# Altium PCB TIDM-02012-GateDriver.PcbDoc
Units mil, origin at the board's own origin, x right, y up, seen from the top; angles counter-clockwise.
Board outline 2300 x 940 mil, 4 copper layers (Top Layer, Layer 1, Layer 2, Bottom Layer), stack 52.2 mil thick; 39 components, 15 nets, 65 pads, 17 vias.
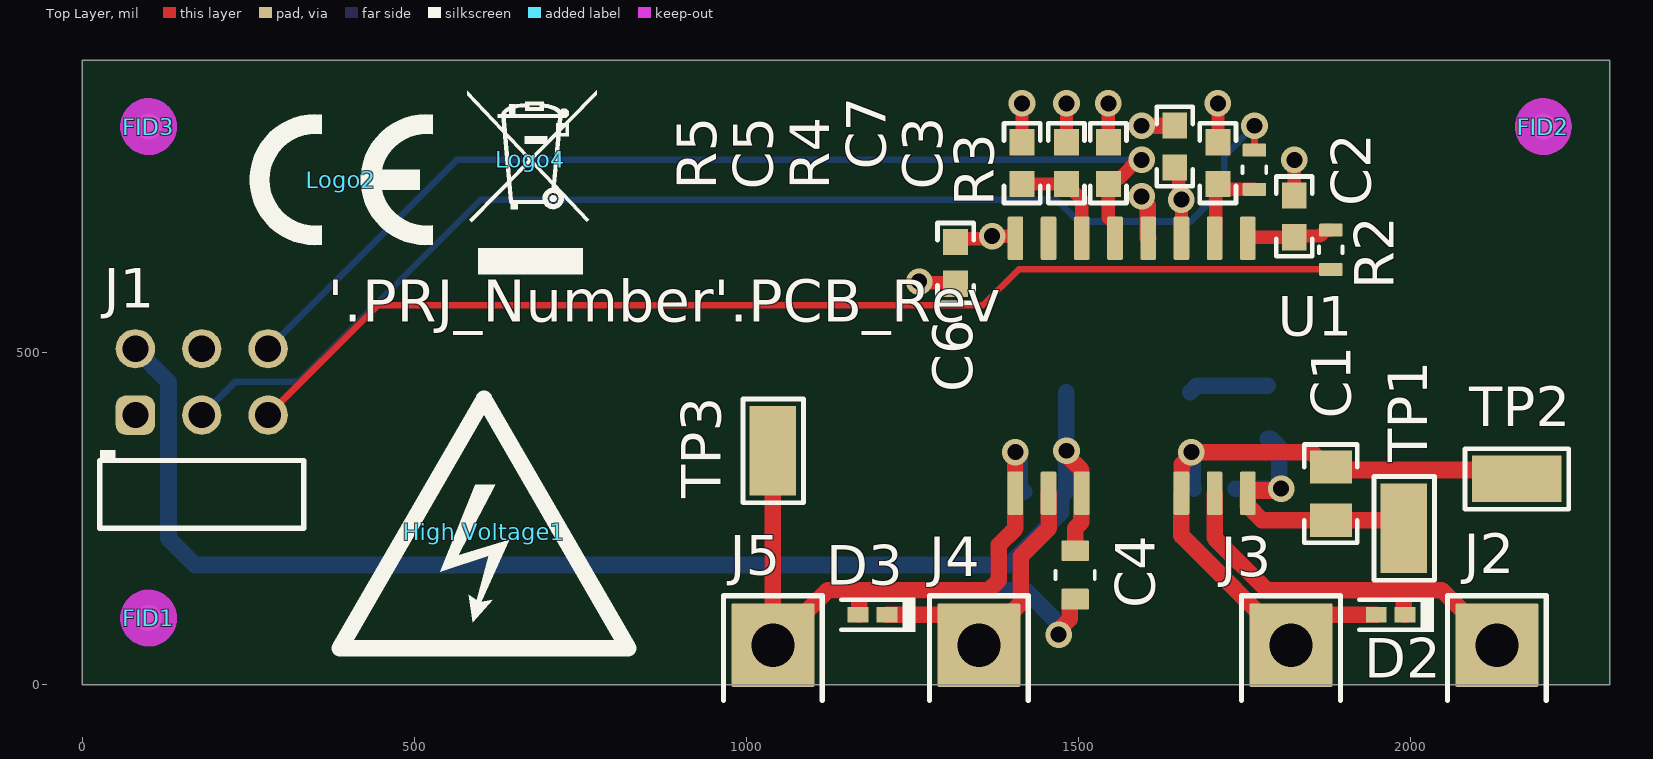
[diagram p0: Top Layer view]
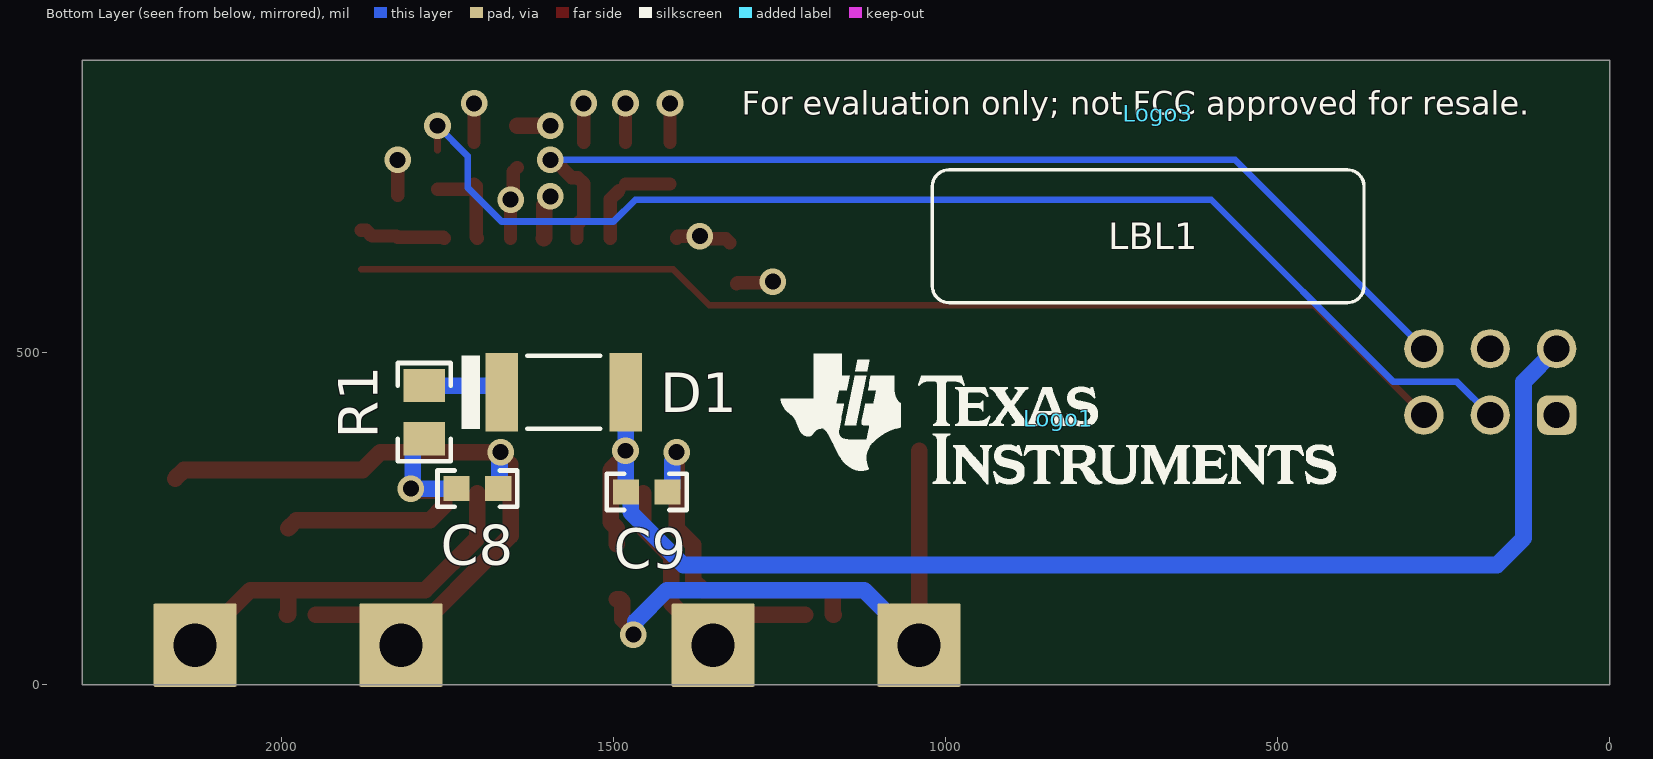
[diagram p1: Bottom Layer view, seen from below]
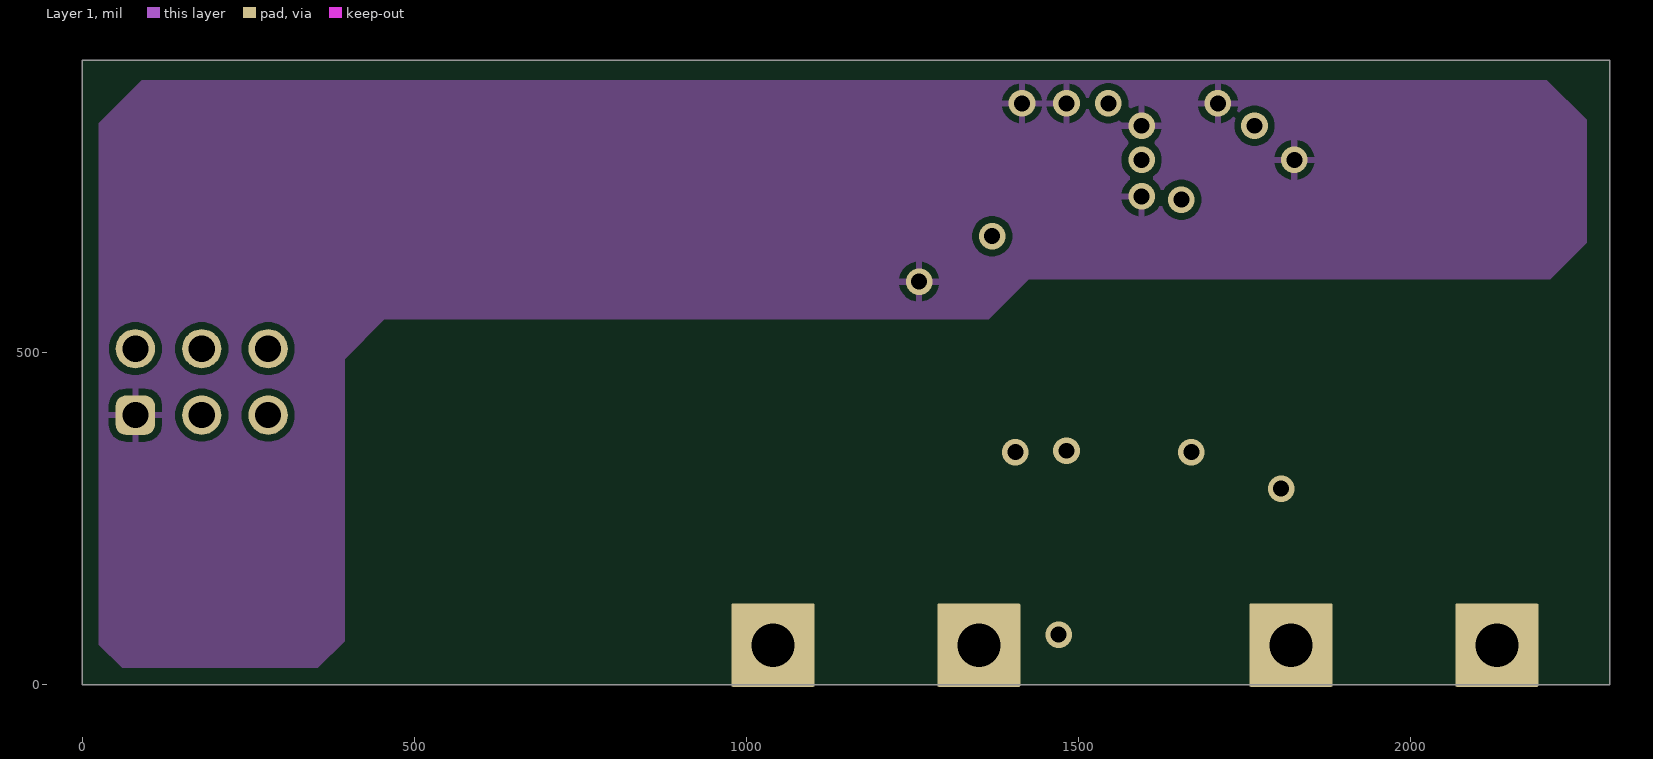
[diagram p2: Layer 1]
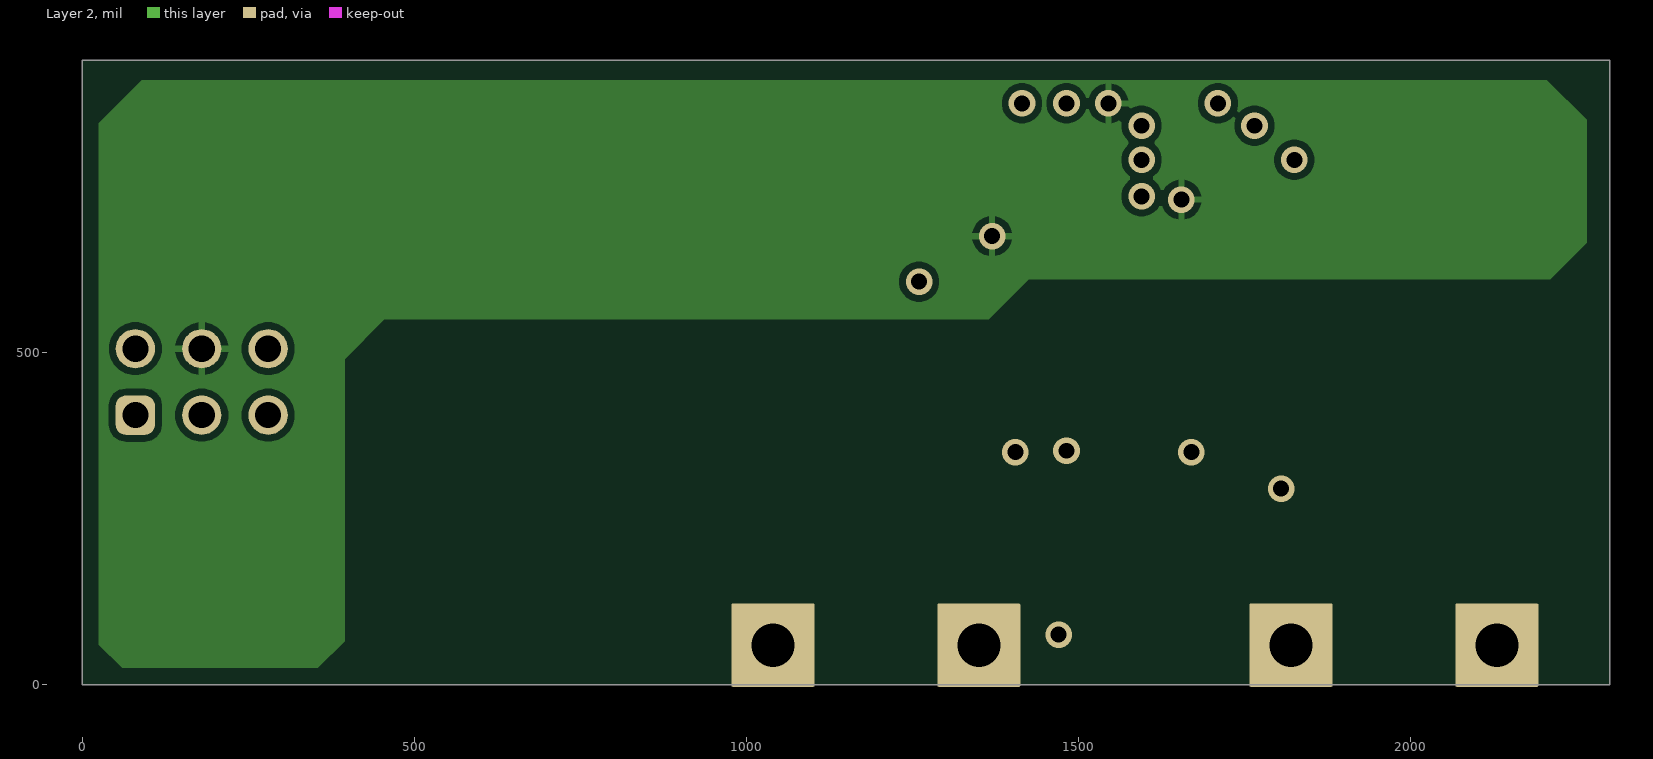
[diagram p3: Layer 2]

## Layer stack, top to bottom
Top Solder: solder mask 0.4, Solder Resist, Dk 3.5
Top Layer: signal copper 2.8
Dielectric 1: prepreg 5.6, PP-006, Dk 4.1
Layer 1: signal copper 2.8
Dielectric1: core 29.8, FR-4 High Tg, Dk 4.8
Layer 2: signal copper 2.8
Dielectric 2: prepreg 5.6, PP-006, Dk 4.1
Bottom Layer: signal copper 2.8
Bottom Solder: solder mask 0.4, Solder Resist, Dk 3.5

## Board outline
0,0 0,940 2300,940 2300,0

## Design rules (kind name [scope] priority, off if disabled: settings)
AcuteAngle [All] p1: minimum=4.50000000000000E+0001 checktracksonly=FALSE
AssemblyTestPointUsage [All] p1: valid=2
BoardOutlineClearance BoardOutlineClearance_MountingHoles [OnCopper and InComponentClass('Mounting Holes')] p1: gap=39.37 ignorepadtopadclearanceinfootprint=FALSE
BoardOutlineClearance BoardOutlineClearance_Poly [OnCopper and IsPoly] p2: gap=25 ignorepadtopadclearanceinfootprint=FALSE
BoardOutlineClearance [OnCopper and Not InComponentClass('Logo') and not InComponentClass('FiducialMark') and not InRegion(1000,500,4000,800) and not InPoly] p3: gap=40 ignorepadtopadclearanceinfootprint=FALSE
Clearance Clearance_Keepouts [((IsTrack Or IsArc) And Not InPoly) And IsFree and IsKeepOut vs ((IsTrack Or IsArc) And Not InPoly) And IsFree and IsKeepOut] p1: gap=0 ignorepadtopadclearanceinfootprint=FALSE
Clearance Clearance_Poly [InPolygon] p2: gap=10 ignorepadtopadclearanceinfootprint=TRUE
Clearance Clearance_FiducialMark [IsKeepOut and InComponentClass('FiducialMark') vs IsPad and InComponentClass('FiducialMark')] p3: gap=0 ignorepadtopadclearanceinfootprint=FALSE
Clearance [All] p4: gap=7.87 ignorepadtopadclearanceinfootprint=TRUE
ComponentClearance ComponentClearance_MountingHoles_FiducialMarks [InComponentClass('Mounting Holes') vs InComponentClass('FiducialMark')] p1: gap=50 collisioncheckmode=3 verticalgap=10 showdistances=FALSE
ComponentClearance ComponentClearance_Shunt [InComponentClass('Header') vs InComponentClass('Shunt')] p2: gap=0 collisioncheckmode=3 verticalgap=0 showdistances=FALSE
ComponentClearance ComponentClearance_Logo [InComponentClass('Logo')] p3: gap=30 collisioncheckmode=3 verticalgap=10 showdistances=FALSE
ComponentClearance ComponentClearance_ScrewToNut [(HasFootprint('NY PMS 440 0025 PH')) vs (HasFootprint('Keystone_1902C'))] p4: gap=5 collisioncheckmode=3 verticalgap=10 showdistances=FALSE
ComponentClearance ComponentClearance_MountingHoles [InComponentClass('Mounting Holes')] p5: gap=100 collisioncheckmode=3 verticalgap=100000 showdistances=FALSE
ComponentClearance ComponentClearance_SmallPassives [HasFootprint('0201*') or HasFootprint('0402*') or HasFootprint('0508') or HasFootprint('0603*') or HasFootprint('0612') or HasFootprint('0805*') or HasFootprint('0815*') or HasFootprint('0830*') or HasFootprint('1206*') or HasFootprint('1210*') or HasFootprint('1808*') or HasFootprint('1812*') or HasFootprint('1825*') or HasFootprint('2010*') or HasFootprint('2220*') or HasFootprint('2225*') or HasFootprint('2512*') or HasFootprint('2728*') or HasFootprint('3518*') vs HasFootprint('0201*') or HasFootprint('0402*') or HasFootprint('0508') or HasFootprint('0603*') or HasFootprint('0612') or HasFootprint('0805*') or HasFootprint('0815*') or HasFootprint('0830*') or HasFootprint('1206*') or HasFootprint('1210*') or HasFootprint('1808*') or HasFootprint('1812*') or HasFootprint('1825*') or HasFootprint('2010*') or HasFootprint('2220*') or HasFootprint('2225*') or HasFootprint('2512*') or HasFootprint('2728*') or HasFootprint('3518*')] p6: gap=14.96 collisioncheckmode=3 verticalgap=10 showdistances=FALSE
ComponentClearance ComponentClearance_THtoSMT [IsThruComponent vs IsSMTComponent] p7: gap=30 collisioncheckmode=3 verticalgap=30 showdistances=FALSE
ComponentClearance ComponentClearance_THtoTH [IsThruComponent vs IsThruComponent] p8: gap=20 collisioncheckmode=3 verticalgap=30 showdistances=FALSE
ComponentClearance [All] p9: gap=20 collisioncheckmode=3 verticalgap=10 showdistances=FALSE
DiffPairsRouting [All] p1: maxlimit=100 minlimit=10 mostfreqgap=10 toplayer_minwidth=15 toplayer_maxwidth=15 toplayer_prefwidth=15 midlayer1_minwidth=15 midlayer1_maxwidth=15 midlayer1_prefwidth=15 midlayer2_minwidth=15 midlayer2_maxwidth=15 midlayer2_prefwidth=15 bottomlayer_minwidth=15 bottomlayer_maxwidth=15 bottomlayer_prefwidth=15 maxuncoupledlength=1000
FabricationTestPointUsage TestPointUsage [All] p1: valid=2 allowmultiple=FALSE
FabricationTestpoint Testpoint [All] p1: side=3 testpointundercomponent=TRUE minsize=40 maxsize=100 preferedsize=60 minholesize=0 maxholesize=40 preferedholesize=32 testpointgrid=1 allowsidetop=TRUE allowsidebottom=TRUE usegrid=TRUE gridtolerance=0.01
FanoutControl Fanout_LCC [IsLCC] p1: bgadir=Out bgaviamode=Centered fanoutstyle=Auto fanoutdirection=Alternating viagrid=1 // Fanout_LCC (Default Rule)
FanoutControl Fanout_BGA [IsBGA] p2: bgadir=Out bgaviamode=Centered fanoutstyle=Auto fanoutdirection=Alternating viagrid=1 // Fanout_BGA (Default Rule)
FanoutControl Fanout_Default [All] p4: bgadir=Out bgaviamode=Centered fanoutstyle=Auto fanoutdirection=Alternating viagrid=1 // Fanout_Default (Default Rule)
FanoutControl Fanout_Small [(CompPinCount < 5)] p5: bgadir=Out bgaviamode=Centered fanoutstyle=Auto fanoutdirection=OutThenIn viagrid=1 // Fanout_Small (Default Rule)
HoleSize [All] p1: absolutevalues=TRUE maxlimit=251 minlimit=7.87 maxpercent=80.000 minpercent=20.000
MinimumAnnularRing MinimumAnnularRing_ThermalPadVias [IsVia and InAnyComponent] p1: minimumring=5.91
MinimumAnnularRing [All] p2: minimumring=7.87
MinimumSolderMaskSliver MinimumSolderMaskSliver_Logo [InComponentClass('Logo') vs InComponentClass('Logo')] p1: minsoldermaskwidth=0.7
MinimumSolderMaskSliver [All] p2: minsoldermaskwidth=3.94
PlaneConnect [All] p1: planeconnectstyle=Relief reliefexpansion=10 reliefentries=4 reliefconductorwidth=10 reliefairgap=10
PolygonConnect [All] p1: connectstyle=Relief reliefconductorwidth=10 reliefentries=4 polygonreliefangle="90 Angle" airgapwidth=10
RoutingVias ThermalPadVias [IsVia and InAnyComponent] p1: holewidth=7.87 width=19.68 viastyle="Through Hole" minholewidth=7.87 minwidth=19.68 maxholewidth=12.99 maxwidth=23.62
RoutingVias [All] p2: holewidth=16 width=34 viastyle="Through Hole" minholewidth=7.87 minwidth=24 maxholewidth=40 maxwidth=65
SilkToBoardRegionClearance [Not ((IsComment or IsDesignator) And (Hide <> 'False')) and not InRegion(1000,500,4000,800)] p1:
SilkToSilkClearance SilkToSilkClearance_Pb-FreeLogo [(HasFootprint('Pb-Free_Overlay_Medium') OR HasFootprint('Pb-Free_Overlay_Small')) vs (HasFootprint('Pb-Free_Overlay_Medium') OR HasFootprint('Pb-Free_Overlay_Small'))] p1: silktosilkclearance=0
SilkToSilkClearance [All] p2: silktosilkclearance=3.94
SilkToSolderMaskClearance SilkToComponentPadClearance [(IsPad or IsFill or IsRegion) and InAnycomponent] p1: minsilkscreentomaskgap=5 clearancetoexposedcopper=TRUE
SilkToSolderMaskClearance "Silk to Solder Mask Opening" [All] p2: minsilkscreentomaskgap=3.94 clearancetoexposedcopper=FALSE
SolderMaskExpansion [All] p1: expansion=1.97 istentingtop=FALSE
UnRoutedNet [All] p1: checkbadconnections=TRUE
Width [All] p1: maxlimit=100 minlimit=6 preferedwidth=10 checkconnectedcopper=TRUE
14 further rules are at their usual default settings.

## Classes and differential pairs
component class Header: J1
component class Logo: Logo1
component class TIDM-02012-GateDriver_Hardware: FID1 FID2 FID3 "High Voltage1" LBL1 Logo1 Logo2 Logo3 Logo4 ZZ1 ZZ2 ZZ3 ZZ4
component class FiducialMark: FID1 FID2 FID3
component class AssemblyNote: ZZ1 ZZ2 ZZ3 ZZ4
component class Label: LBL1

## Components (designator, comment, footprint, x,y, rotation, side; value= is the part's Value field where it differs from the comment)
C1 "C2012X7R1H225M125AC" 0805_HV 1880,287.38 r90 top value=2.2uF
C2 "C0603C470J1GACAUTO" 0603 1825,705 r90 top value=47pF
C3 "C0603C470J1GACAUTO" 0603 1710,785 r90 top value=47pF
C4 "C2012X7R1H475K125AC" FP-C2012X7R1H475K125AC_0805-MFG 1495,165 r90 top
C5 "CGA3E2X7R2A222K080AA" 0603 1481.98,785 r90 top value=2200pF
C6 "CGA3E1X7R1E105M080AC" 0603 1315,635 r270 top value=1uF
C7 "C0603C104K5RACTU" 0603 1645,810 r90 top value=0.1uF
C8 "C0603C104K5RACTU" 0603 1705,295 r0 bottom value=0.1uF
C9 "C0603C104K5RACTU" 0603 1450,290 r0 bottom value=0.1uF
D1 "BYM10-1000-E3/97" DO-213AB 1575,440 r180 bottom value=1000V
D2 "RB520SM-40FH" SOD-523 1970,105 r180 top value=45V
D3 "RB520SM-40FH" SOD-523 1190,105 r180 top value=45V
FID1 "Fiducial" Fiducial10-20 100,100 r0 top
FID2 "Fiducial" Fiducial10-20 2200,840 r90 top
FID3 "Fiducial" Fiducial10-20 100,840 r0 top
"High Voltage1" "DANGER HIGH VOLTAGE" IEC_HighVoltage_Medium 605,230 r0 top
J1 "90122-0763" Molex_90122-0763 180,455.59 r90 top locked
J2 "3620-2-32-15-00-00-08-0" Mill-Max_3620-2-32-xx-00-00-08-0 2130,-40 r0 top locked
J3 "3620-2-32-15-00-00-08-0" Mill-Max_3620-2-32-xx-00-00-08-0 1820,-40 r0 top locked
J4 "3620-2-32-15-00-00-08-0" Mill-Max_3620-2-32-xx-00-00-08-0 1350,-40 r0 top locked
J5 "3620-2-32-15-00-00-08-0" Mill-Max_3620-2-32-xx-00-00-08-0 1040,-40 r0 top locked
LBL1 "THT-14-423-10" Label_650x200 695,675 r180 bottom
Logo1 "Texas Instruments" TI_Stacked_Overlay_Small 830,400 r180 bottom
Logo2 "CE Mark" CE_Mark_5mm 390,760 r0 top
Logo3 "FCC disclaimer" FCC_disclaimer 680,860 r180 bottom
Logo4 "WEEE logo" WEEE_Minimum 675,790 r0 top
R1 "ERJ-6BQF1R0V" 0805_HV 1785,410 r90 bottom value=1.00
R2 "CRCW06030000Z0EBC" FP-CRCW06030000Z0EBC_0603-MFG 1880,654.53 r90 top value=0
R3 "CRCW06030000Z0EBC" FP-CRCW06030000Z0EBC_0603-MFG 1765,775 r270 top value=0
R4 "RC0603FR-0710KL" 0603 1545,785 r270 top value=10.0k
R5 "RC0603FR-073K09L" 0603 1415,785 r270 top value=3.09k
TP1 "5015" Testpoint_Keystone_Miniature 1990,235.14 r90 top
TP2 "5015" Testpoint_Keystone_Miniature 2160,310 r0 top
TP3 "5015" Testpoint_Keystone_Miniature 1040,351.94 r90 top
U1 "UCC21530QDWKQ1" DWK0014A 1580,480 r270 top
ZZ1 "This Assembly Note is for PCB labels only" AssemblyNoteLabel 130,1708 r0 top
ZZ2 "These assemblies are ESD sensitive, ESD precautions shall be observed." AssemblyNote 130,1599.11 r0 top
ZZ3 "These assemblies must be clean and free from flux and all contaminants. Use of no clean flux is not acceptable." AssemblyNote 130,1510.56 r0 top
ZZ4 "These assemblies must comply with workmanship standards IPC-A-610 Class 2, unless otherwise specified." AssemblyNote 130,1422 r0 top

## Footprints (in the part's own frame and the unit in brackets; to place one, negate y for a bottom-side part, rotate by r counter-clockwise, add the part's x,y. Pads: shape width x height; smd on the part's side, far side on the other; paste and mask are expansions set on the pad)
0603 [mm] "0603 from SM-752 data"
  rect 1x0.95 smd: 1(-0.8,0) 2(0.8,0)
  silkscreen extent -1.52,-0.69 1.52,0.69, body extent -0.87,-0.47 0.87,0.47, height 1
0805_HV [mil] "0805 with 30mil clearance between pads"
  rect 50x63 smd: 1(-40,0) 2(40,0)
  silkscreen extent -74,-40 74,40, body extent -43,-29 43,29, height 57
AssemblyNote [mil] "Assembly Note"
AssemblyNoteLabel [mil] "Assembly Note for PCB Labels"
CE_Mark_5mm [mil] "Minimum text height for CE Mark"
  silkscreen extent -138,-98 138,98
DO-213AB [mm] "VISHAY"
  rect 1.25x3 smd: 1(-2.375,0) 2(2.375,0)
  silkscreen extent -3.9,-1.4 1.4,1.4, body extent -2.6,-1.34 2.6,1.33, height 2.67
DWK0014A [mm] "SOIC-14"
  rrect17% 1.65x0.6 smd: 1(-4.875,4.445) 2(-4.875,3.175) 3(-4.875,1.905) 4(-4.875,0.635) 5(-4.875,-0.635) 6(-4.875,-1.905) 7(-4.875,-3.175) 8(-4.875,-4.445) 9(4.875,-4.445) 10(4.875,-3.175) 11(4.875,-1.905) 14(4.875,1.905) 15(4.875,3.175) 16(4.875,4.445)
  body extent -5.17,-5.15 5.17,5.15, height 2.59
FCC_disclaimer [mil]
Fiducial10-20 [mm]
  round 1 smd mask+0.5: 1(0,0)
  Top Layer keep-out circle w1.178: c0,0 r0.5
FP-C2012X7R1H475K125AC_0805-MFG [mm]
  rrect13% 0.8x1.05 smd paste+0 mask+0: 1(-0.925,0) 2(0.925,0)
  silkscreen extent -0.15,-0.75 0.15,0.75, body extent -1,-0.63 1,0.63, height 1.5
FP-CRCW06030000Z0EBC_0603-MFG [mm]
  rrect20% 0.5x0.9 smd paste+0 mask+0: 1(-0.75,0) 2(0.75,0)
  silkscreen extent -0.13,-0.45 0.13,0.45, body extent -1.1,-0.55 1.1,0.55, height 0.25
IEC_HighVoltage_Medium [mil]
  silkscreen extent -217,-176 217,200
Label_650x200 [mil] "Thermal Transfer Label"
  round 1 on Mech14: 0(0,0)
  silkscreen extent -325,-100 325,100, body extent -325,-100 325,100, height 1
Mill-Max_3620-2-32-xx-00-00-08-0 [mm] "PCB Pin, 0.04\" DIA, R/A, Edge-Mount"
  rrect3% 3.18x3.18 hole 1.65: 1(0,2.52)
  silkscreen extent -1.89,0.41 1.89,4.41, body extent -1.59,-5.06 1.59,4.11, height 0.81
Molex_90122-0763 [mm] "Header, 2.54mm, 3x2, R/A, TH"
  rrect50% 1.5x1.5 hole 1: 1(-1.27,2.54)
  round 1.5 hole 1: 2(1.27,2.54) 3(-1.27,0) 4(1.27,0) 5(-1.27,-2.54) 6(1.27,-2.54)
  silkscreen extent -5.6,-3.9 -2.6,3.9, body extent -12.27,-3.81 1.57,3.81, height 6.15
SOD-523 [mm] "NXP Semiconductor recommended land pattern, nominal STEP model"
  rect 0.8x0.6 smd paste-0.05: 1(-0.55,0) 2(0.55,0)
  silkscreen extent -1.65,-0.66 1.2,0.66, body extent -0.8,-0.4 0.8,0.4, height 0.72
Testpoint_Keystone_Miniature [mil] "Miniature SMT test point"
  rect 135x70 smd: 1(0,0)
  silkscreen extent -78,-46 78,45, body extent -52,-20 52,20, height 61
TI_Stacked_Overlay_Small [mil]
  silkscreen extent -418,-98 418,98
WEEE_Minimum [mil] "WEEElie bin"
  silkscreen extent -95,-172 99,104

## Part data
C1: library part CMP-0007878-2, "CAP, CERM, 2.2 uF, 50 V, +/- 20%, X7R, 0805", Cap_Case=0805, Manufacturer=TDK, Supplier Part Number 1=445-5969-1-ND, TempCo=X7R, Tolerance_%=20%, Value1=Unknown, Value2=50V, ValueDisplayed=2.2uF
C2 C3: library part CMP-0085572-1, "CAP, CERM, 47 pF, 100 V,+/- 5%, C0G/NP0, AEC-Q200 Grade 1, 0603", Cap_Case=0603, Manufacturer=Kemet, TempCo=C0G/NP0, Tolerance_%=5%, Value2=100V, ValueDisplayed=47pF
C4: library part CMP-0088943-1, "4.7µF ±10% 50V Ceramic Capacitor X7R 0805 (2012 Metric)", Digikey Part Number=445-C2012X7R1H475K125ACCT-ND, Manufacturer=TDK, Mouser Part Number=810-C2012X7R475K125C, Operating Temperature Range="-55°C to +125°C", TempCo=15%, Temperature Characteristic=X7R, Tolerance_%=10%, ValueDisplayed=4.7uF
C5: library part CMP-0007085-4, "CAP, CERM, 2200 pF, 100 V, +/- 10%, X7R, AEC-Q200 Grade 1, 0603", Cap_Case=0603, Manufacturer=TDK, Supplier Part Number 1=445-5808-1-ND, TempCo=X7R, Tolerance_%=10%, Value1="0.923948 ohm", Value2=100V, ValueDisplayed=2200pF
C6: library part CMP-0082113-1, "CAP, CERM, 1 µF, 25 V,+/- 20%, X7R, AEC-Q200 Grade 1, 0603", Cap_Case=0603, Manufacturer=TDK, Supplier Part Number 1=445-12548-2-ND, TempCo=X7R, Tolerance_%=20%, Value2=25V, ValueDisplayed=1µF
C7 C8 C9: library part CMP-0006861-4, "CAP, CERM, 0.1 uF, 50 V, +/- 10%, X7R, 0603", Cap_Case=0603, Manufacturer=Kemet, Supplier Part Number 1=399-5089-1-ND, TempCo=X7R, Tolerance_%=10%, Value1=Unknown, Value2=50V, ValueDisplayed=0.1uF
D1: library part CMP-0076899-2, "Diode, P-N, 1000 V, 1 A, DO-213AB", Manufacturer=Vishay-Semiconductor, Value1=1A, Value2=1.2V
D2 D3: library part CMP-0077062-3, "Diode, Schottky, 45 V, 0.2 A, AEC-Q101, SOD-523", Manufacturer=Rohm, Value1=0.2A, Value2=0.55V
FID1 FID2 FID3: library part CMP-0077181-1, "Fiducial mark.  There is nothing to buy or mount.", Manufacturer=N/A
"High Voltage1": library part CMP-0074835-1, "IEC 61010-1 High Voltage Warning"
J1: library part CMP-0077741-2, "Header, 2.54mm, 3x2, Gold, R/A, TH", Color=Black, Current_A=3A, Manufacturer=Molex, Supplier Part Number 1=WM50030-06-ND, Voltage_V=350V
J2 J3 J4 J5: library part CMP-0055044-1, Manufacturer=Mill-Max, Supplier Part Number 1=ED1278-ND
LBL1: library part CMP-0003625-1, "Thermal Transfer Printable Labels, 0.650\" W x 0.200\" H - 10,000 per roll", Manufacturer=Brady, Supplier Part Number 1=97C5133
Logo1: library part CMP-0074838-1, "Texas Instrument Corporate Signature"
Logo2: library part CMP-0074844-1
Logo3: library part CMP-0074847-1, "FCC_disclaimer"
Logo4: library part CMP-0074769-1
R1: library part CMP-0074786-1, "RES, 1.00, 1%, 0.333 W, AEC-Q200 Grade 1, 0805", Manufacturer=Panasonic, Power_W=333mW, Supplier Part Number 1=P17499CT-ND, TempCo="200 ppm/C", Tolerance_%=1%, Value2=0.333W, Value_Code=1R00, ValueDisplayed=1.00
R2 R3: library part CMP-0093667-1, "CRCW Thick Film Commodity Chip Resistor Jumper 0603 Size 0 Ohm 0.1 W 2-Pin SMD Paper T/R", Digikey Part Number=541-4013-1-ND, Manufacturer=Vishay, Mouser Part Number=71-CRCW06030000Z0EBC, Operating Temperature Range="-55°C to +155°C", Power_W=100mW
R4: library part CMP-0022746-5, "RES, 10.0 k, 1%, 0.1 W, 0603", Manufacturer=Yageo, Power_W=100mW, Supplier Part Number 1=311-10.0KHRCT-ND, TempCo="100 ppm/C", Tolerance_%=1%, Value2=0.1W, Value_Code=10k0, ValueDisplayed=10.0k
R5: library part CMP-0023077-5, "RES, 3.09 k, 1%, 0.1 W, 0603", Manufacturer=Yageo, Power_W=100mW, Supplier Part Number 1=311-3.09KHRCT-ND, TempCo="100 ppm/C", Tolerance_%=1%, Value2=0.1W, Value_Code=3k09, ValueDisplayed=3.09k
TP1 TP2 TP3: library part CMP-0055152-1, "Test Point, Miniature, SMT", Manufacturer=Keystone, Supplier Part Number 1=36-5015TR-ND
U1: library part CMP-0083996-1, "4-A, 6-A, 5.7-kVRMS Isolated Dual-Channel Gate Driver with Enable, DWK0014A (SOIC-14)", Alternate Manufacturer="Texas Instruments", Alternate PartNumber=UCC21530QDWKRQ1
ZZ1: library part CMP-0003616-3
ZZ2: library part CMP-0077236-1
ZZ3: library part CMP-0077237-1
ZZ4: library part CMP-0077238-1

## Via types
v1: diameter 40, hole 24, Top Layer to Bottom Layer, 17 vias

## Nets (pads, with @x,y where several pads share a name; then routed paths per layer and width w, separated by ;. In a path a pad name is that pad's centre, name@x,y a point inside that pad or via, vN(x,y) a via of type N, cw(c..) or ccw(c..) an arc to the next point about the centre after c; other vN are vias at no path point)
EN: J1.6 R4.2 U1.5 | length 1584.2
  Top Layer w20: U1.5 1555,692.6 1545,702.6 R4.2 1545,754.49 1553.7,763.19 1562.78,763.19 1589.59,790 v1(1595,790)
  Bottom Layer w10: J1.6 564.41,790 v1(1595,790)
G_1: D2.1 J2.1 U1.15 | length 597.7
  Top Layer w25: U1.15 1705,220.7 1783.52,142.19 1990,142.19 ; D2.1 1990.69,105 1990,105.69 1990,142.19 ; J2.1 2047.03,142.19 1990,142.19
G_2: D3.1 J4.1 U1.10 | length 429.7
  Top Layer w25: D3.1 1304.21,105 J4.1 1412.89,122.11 1412.89,192.89 1455,235 U1.10
GND_Iso: C2.2 C3.2 C5.2 C6.2 C7.2 J1.1 R5.1 U1.4 | length 402.5
  Top Layer w20: v1(1260,606.5) 1261.5,605 1313.5,605 C6.2 ; R5.1 v1(1415,875) ; C5.2 v1(1481.98,875) ; C3.2 v1(1710,875) ; C2.2 v1(1825,790)
  Top Layer w25: v1(1595,735) 1595,730.94 1604.31,721.63 1604.31,672.62 U1.4 ; v1(1595,841.34) 1595.08,841.42 1644.92,841.42 C7.2
NetC1_1: C1.1 C8.2 R1.1 TP1.1 U1.16 | length 477.6
  Top Layer w25: v1(1805,295) 1802.13,292.13 1755.69,292.13 1755,291.44 U1.16 1755,268.78 1776.4,247.38 C1.1 1977.76,247.38 TP1.1
  Bottom Layer w25: C8.2 v1(1805,295) 1802.13,297.87 1802.13,357.5 1789.63,370 R1.1
NetC2_1: C2.1 R2.2 U1.1 | length 130
  Top Layer w20: U1.1 1756.57,673.5 C2.1 1826.81,675.31 1863.7,675.31 1872.44,684.06 R2.2
NetC3_1: C3.1 R3.2 U1.2 | length 142
  Top Layer w20: U1.2 1706.81,673.74 1706.81,750.31 C3.1 1717.87,745.63 1764.84,745.63 R3.2
NetC5_1: C5.1 R5.2 U1.6 | length 144.4
  Top Layer w20: R5.2 C5.1 ; C5.1@1491.66,743.82 1505,730.48 U1.6
NetD1_1: D1.1 R1.2 | length 120.6
  Bottom Layer w25: D1.1 1678.5,450 R1.2
PWM_H: J1.5 R2.1 | length 1690.9
  Top Layer w10: J1.5 445.35,570.94 1355.94,570.94 1410,625 R2.1
PWM_L: J1.3 R3.1 | length 1857.6
  Top Layer w10: R3.1 v1(1765,841.34)
  Bottom Layer w10: J1.3 230.1,455.69 325.69,455.69 600,730 1467.13,730 1500,697.13 1668.62,697.13 1719.63,748.14 1719.63,795.97 v1(1765,841.34)
S_1: C1.2 C8.1 D2.2 J3.1 TP2.1 U1.14 | length 1075.7
  Top Layer w25: D2.2 1865.79,105 J3.1 1655,224.21 U1.14 1655.69,288.76 1655.69,331.63 1670,345.94 v1(1670,350) 1851,350 1851,349.88 1877.87,323.01 2146.99,323.01 TP2.1
  Bottom Layer w25: v1(1670,350) 1671.75,348.25 1671.75,296.75 C8.1
S_2: C4.1 C9.1 D3.2 J5.1 TP3.1 U1.9 | length 1550.4
  Top Layer w25: TP3.1 J5.1 1122.97,142.19 1170,142.19 ; D3.2 1169.31,105 1170,105.69 1170,142.19 ; v1(1405,350) U1.9 1405,235 1380.02,210.02 1380.02,156.83 1365.38,142.19 1170,142.19 ; v1(1470,75) 1470,81.76 1486.83,98.6 1486.83,125.33 1490.08,128.58 C4.1
  Bottom Layer w25: J5.1 1122.97,142.19 1419.94,142.19 1467.13,94.99 1467.13,77.87 v1(1470,75) ; v1(1405,350) 1405,343.24 1411.32,336.92 1411.32,296.2 1417.52,290 C9.1
VCC33: C6.1 C7.1 J1.4 R4.1 U1.3 U1.8 | length 255.4
  Top Layer w20: C6.1@1325,665 1331.17,671.17 1366.17,671.17 v1(1370,675) 1403.19,675 1405,673.19 U1.8 ; R4.1 v1(1545,875) ; C7.1 1651.17,772.33 1651.17,733.83 v1(1655,730) U1.3
VDD_Driver: C4.2 C9.2 D1.2 J1.2 U1.11 | length 2036.9
  Top Layer w25: v1(1481.98,351.94) 1481.98,345.18 1504.31,322.84 U1.11@1504.31,288.76 ; C4.2@1495,211.5 1495,235.14 1504.31,244.45 U1.11@1504.31,287.38
  Bottom Layer w25: J1.2 129.9,455.69 129.9,220 169.9,180 1395,180 1474.31,259.31 1474.31,283.8 1480.51,290 C9.2 1481.5,351.46 v1(1481.98,351.94) 1481.74,352.18 1481.74,439.76 D1.2
pads on no net: FID1.1 FID2.1 FID3.1 LBL1.0 U1.7

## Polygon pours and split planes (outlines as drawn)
GND_Iso on Layer 1 "LAYER_1_GND_ISO_P000" (solid, pour order 0): 25,60 60,25 355,25 395,65 395,490 455,550 455.1,549.9 1364.9,549.9 1425,610 2210,610 2265,665 2265,850 2205,910 90,910 25,845
VCC33 on Layer 2 "LAYER_2_VCC33_P001" (solid, pour order 1): 25,60 60,25 355,25 395,65 395,490 455,550 455.1,549.9 1364.9,549.9 1425,610 2210,610 2265,665 2265,850 2205,910 90,910 25,845

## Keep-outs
Keep-Out Layer:
  text ".Layer_Name" at 577,-858.49 h60

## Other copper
Top Layer:
  text ".Layer_Name" at 577,-858.49 h60
Bottom Layer:
  text ".Layer_Name" at 577,-858.49 h60

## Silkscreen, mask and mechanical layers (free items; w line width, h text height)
Top Overlay:
  text "'.PRJ_Number'.PCB_Rev" at 370,525 h108.27
  text ".Layer_Name" at 577,-858.49 h60
Bottom Overlay:
  text ".Layer_Name" at 577,-858.49 h60
Top Paste:
  text ".Layer_Name" at 577,-858.49 h60
Bottom Paste:
  text ".Layer_Name" at 577,-858.49 h60
Top Solder:
  text ".Layer_Name" at 577,-858.49 h60
  text ".Layer_Name" at 577,-858.49 h60
Bottom Solder:
  text ".Layer_Name" at 577,-858.49 h60
Drill Guide:
  text ".Layer_Name" at 577,-858.49 h60
M1 Board Outline:
  the board outline again, w10
  text ".Layer_Name" at 577,-858.49 h60
M2 Board Dimensions:
  rectangle: 0,-275 125,-150
  rectangle: 125,-400 500,-275
  lines w7: 0,-275 1000,-275 ; 125,-400 125,-150 ; 250,-400 250,-150 ; 500,-400 500,-150 ; 750,-400 750,-150 ; 0,-400 1000,-400 1000,-150 0,-150 0,-400
  text ".Layer_Name" at 577,-858.49 h60
M3 3D STEP Top:
  text ".Layer_Name" at 577,-858.49 h60
M4 3D STEP Bottom:
  text ".Layer_Name" at 577,-858.49 h60
M5 Assembly Top:
  lines w10: -292,-930.17 6308,-930.17 ; -292,-726.83 6310,-726.83 ; -292,-523.5 -292,-1133.5 3713,-1133.5 6310,-1133.5 6310,-523.5 -291.5,-523.5 -291.5,-1133.5 1284,-1133.5 ; 2173,-1133.5 2173,-523.5 ; 3440,-726.83 3440,-523.5 ; 4280,-726.83 4280,-523.5 ; 4902,-1140 4902,-937.17
  text "COMPONENTS MARKED 'DNP' SHOULD NOT BE POPULATED." at 2973.26,45.95 h60
  text "ASSEMBLY VARIANT:" at 2972.76,-69.55 h60
  text ".VariantName" at 4008.76,-69.55 h60
  text "PCB VIEWED FROM TOP SIDE" at -228.5,-655.67 h60
  text "BOARD #:" at 2248,-655.67 h60
  text ".PRJ_Number" at 2793.5,-655.67 h60
  text "REV:" at 3638,-655.67 h60
  text ".PCB_Rev" at 3929.5,-655.67 h60
  text "SVN REV:" at 4476,-655.67 h60
  text ".VersionControl_RevNumber" at 4982,-655.67 h60
  text "TID #:" at 2248,-859 h60
  text ".TID" at 2793.5,-859 h60
  text "PLOT NAME =" at -228.5,-1064.34 h60
  text ".plot_File_Name" at 577,-1064.34 h60
  text "GENERATED    :" at 2250,-1064.34 h60
  text ".Print_Date" at 3119.5,-1064.34 h60
  text ".Print_Time" at 3848.5,-1064.34 h60
  text "TEXAS INSTRUMENTS" at 5113,-1064.34 h60
M6 Assembly Bottom:
  lines w10: -292.5,-727.33 6309.5,-727.33 ; -290.5,-930.67 6309.5,-930.67 ; 1115.5,-1140.5 1115.5,-937.67 ; 1737.5,-727.33 1737.5,-524 ; 2577.5,-727.33 2577.5,-524 ; 3844.5,-1134 3844.5,-524 ; 4733.5,-1134 6309,-1134 6309,-524 -292.5,-524 -292.5,-1134 2304.5,-1134 6309.5,-1134 6309.5,-524
  text "COMPONENTS MARKED 'DNP' SHOULD NOT BE POPULATED." at 6102,-318 h60
  text ".VariantName" at 5058,-434 h60
  text "ASSEMBLY VARIANT:" at 6097,-434 h60
  text ".VersionControl_RevNumber" at 1035.5,-656.17 h60
  text "SVN REV:" at 1541.5,-656.17 h60
  text ".PCB_Rev" at 2088,-656.17 h60
  text "REV:" at 2379.5,-656.17 h60
  text ".PRJ_Number" at 3224,-656.17 h60
  text "BOARD #:" at 3769.5,-656.17 h60
  text "PCB VIEWED FROM BOTTOM SIDE" at 6246,-656.17 h60
  text ".TID" at 3224,-859.5 h60
  text "TID #:" at 3769.5,-859.5 h60
  text "TEXAS INSTRUMENTS" at 904.5,-1064.84 h60
  text ".Print_Time" at 2169,-1064.84 h60
  text ".Print_Date" at 2898,-1064.84 h60
  text "GENERATED    :" at 3767.5,-1064.84 h60
  text ".plot_File_Name" at 5440.5,-1064.84 h60
  text "PLOT NAME =" at 6246,-1064.84 h60
M9 Title Sheet:
  drawing of 57 lines, arcs and shapes, not listed
  text "1" at 739.84,8036.5 h70
  text "2" at 3235.5,8036.5 h70
  text "3" at 5724.84,8036.5 h70
  text "4" at 8231.51,8036.5 h70
  text "5" at 10730.5,8036.5 h70
  text "6" at 13235.5,8036.5 h70
  text "A" at -416.5,6893.5 h70
  text "A" at 14383.5,6893.5 h70
  text "B" at -416.5,4513.5 h70
  text "B" at 14383.5,4513.5 h70
  text "C" at -416.5,2138.5 h70
  text "C" at 14383.5,2138.5 h70
  text "PROJECT TITLE:" at 11343.5,277.5 h45
  text ".PRJ_Title" at 11393.5,144.17 h70
  text "DESIGNED FOR:" at 11343.5,-23.5 h45
  text ".PRJ_Customer" at 11393.5,-163.5 h70
  text "D" at -416.5,-231.5 h70
  text "D" at 14383.5,-231.5 h70
  text "FILE NAME:" at 11343.5,-323.5 h45
  text ".PCB_File_Name_No_Path" at 11393.5,-443.5 h70
  text "Texas Instruments (TI) and/or its licensors do not warrant the accuracy or completeness of this specification" at 6374,-605.34 h45
  text "ENGINEER:" at 11343.5,-613.5 h45
  text "LAYOUT BY:" at 12848.5,-613.5 h45
  text "or any information contained therein. TI and/or its licensors do not warrant that this design will meet" at 6329.01,-718 h45
  text ".PRJ_Engineer" at 11393.5,-768.49 h70
  text ".PCB_Layout" at 12899,-768.49 h70
  text "the specifications, will be suitable for your application or fit for any particular purpose, or will operate in" at 6329.01,-830.67 h45
  text ".Layer_Name" at 577,-858.49 h60
  text "ALTIUM DESIGNER VERSION:" at 12848.5,-923.5 h45
  text "an implementation. TI and/or its licensors do not warrant that the design is production worthy. You should" at 6329.01,-943.33 h45
  text "completely validate and test your design implementation to confirm the system functionality for your application." at 6374,-1056 h45
  text ".print_Scale" at 11393.5,-1056.83 h70
  text ".Application_BuildNumber" at 12899,-1056.83 h70
  text "1" at 739.84,-1263.5 h70
  text "2" at 3235.5,-1263.5 h70
  text "3" at 5724.84,-1263.5 h70
  text "4" at 8231.51,-1263.5 h70
  text "5" at 10730.5,-1263.5 h70
  text "6" at 13235.5,-1263.5 h70
M10 Fab Notes:
  drawing of 189 lines, arcs and shapes, not listed
  text "DESIGN INFORMATION" at 12382.02,6356.17 h60
  text "MIN. TRACK WIDTH:" at 11737.46,6224.05 h60
  text "8" at 12833.7,6224.05 h60
  text "MIL" at 12988.46,6224.05 h60
  text "7.874" at 12667.32,6102.36 h60
  text "MIN. CLEARANCE:" at 11737.46,6099.92 h60
  text "MIL" at 12988.46,6099.92 h60
  text "MIN. VIA PAD SIZE:" at 11737.46,5975.8 h60
  text "24" at 12803.71,5975.8 h60
  text "MIL" at 12988.46,5975.8 h60
  text "0.05mm (2MIL)" at 12432.46,5845.9 h60
  text "MINIMUM ANNULAR RING" at 11408.23,5837.67 h60
  text "EXTERNAL" at 13140.46,5837.67 h60
  text "PER" at 11608.23,5727.55 h60
  text "IPC-D-275 CLASS 2 LEVEL C" at 11828.23,5727.54 h60
  text "MIL, HOLES" at 13316.46,5627.07 h60
  text "+/-" at 12924,5618.48 h60
  text "+/-" at 13778,5618.48 h60
  text "REGISTRATION TOLERANCES:" at 11408.23,5617.42 h60
  text "METAL" at 12608,5617.42 h60
  text "5" at 13184.2,5617.42 h60
  text "3" at 14017.2,5617.42 h60
  text "MIL" at 14133.46,5617.42 h60
  text "HOLE SIZE TOLERANCE (UNLESS OTHERWISE SPECIFIED):" at 11408.23,5519.1 h60
  text "+/-" at 13778,5516.23 h60
  text "3" at 14017.2,5515.17 h60
  text "MIL" at 14133.46,5515.17 h60
  text "MATERIAL:" at 11333.46,5377.52 h60
  text "FR-4 High Tg" at 12319.9,5249 h60
  text "X" at 12175.46,5241.01 h60
  text "FR-408" at 11754.46,5236.49 h60
  text "OTHER" at 13242.46,5236.49 h60
  text "62 MIL (1.6mm) +/-10%" at 12074.56,5093.46 h60
  text "X" at 11954.46,5091.01 h60
  text "THICKNESS:" at 11408.23,5085.24 h60
  text "OTHER" at 13359.46,5085.24 h60
  text "TOLERANCE:" at 11408.23,4946.92 h60
  text "X" at 12256.46,4946.92 h60
  text "ANSI IPC-6012 TYPE 3 CLASS 2" at 12434.48,4946.92 h60
  text "OTHER +/-" at 12434.46,4802.73 h60
  text "BOW & TWIST:" at 11408.23,4657.54 h60
  text "X" at 12256.46,4657.54 h60
  text "ANSI IPC-6012 TYPE 3 CLASS 2" at 12434.48,4657.54 h60
  text "OTHER +/-" at 12434.46,4510.85 h60
  text "DRILLING:" at 11333.46,4380.23 h60
  text "NC_DRILL FILES" at 13094.46,4275.04 h60
  text "REFERENCE:" at 11408.23,4271.1 h60
  text "X" at 12065.46,4271.01 h60
  text "AS SHOWN" at 12243.46,4271.1 h60
  text "X" at 12966.46,4271.1 h60
  text "OTHER" at 13392.46,4128.85 h60
  text "PTH COPPER THICKNESS:" at 11407.91,4125.32 h60
  text "X" at 12547.14,4125.32 h60
  text "20-30 um" at 12675.14,4125.32 h60
  text "BOARD FINISH:" at 11333.46,3977.73 h60
  text "SILKSCREEN:" at 11488.68,3867.6 h60
  text "X" at 12446.46,3867.6 h60
  text "TOP" at 12563.46,3867.6 h60
  text "X" at 12956.46,3867.6 h60
  text "BOTTOM" at 13074.46,3867.6 h60
  text "SILKSCREEN COLOR:" at 11488.68,3712.41 h60
  text "X" at 12445.46,3712.41 h60
  text "WHITE" at 12563.46,3712.41 h60
  text "OTHER" at 13074.46,3712.41 h60
  text "X" at 12576.46,3568.96 h60
  text "GREEN" at 12694.46,3568.96 h60
  text "OTHER" at 13312.46,3568.96 h60
  text "SOLDER RESIST COLOR:" at 11488.68,3562.1 h60
  text "X" at 12576.46,3414.71 h60
  text "MATTE" at 12694.46,3414.71 h60
  text "SEMI-GLOSS" at 13312,3414.07 h60
  text "IMMERSION GOLD (ENIG)" at 12394.46,3241.94 h60
  text "ENEPIG" at 13732,3234.72 h60
  text "SURFACE FINISH:" at 11333.46,3233.72 h60
  text "X" at 12216.46,3233.72 h60
  text "IMM. TIN/SILVER OR EQUIV" at 11663,3096.4 h60
  text "OTHER" at 13094.46,3092.47 h60
  text "ARRAY/PANEL:" at 11333.46,2937.09 h60
  text "CUT AND TRIM PER M1 BOARD OUTLINE" at 12394.46,2928.87 h60
  text "N.C. ROUTE" at 12394.46,2792.9 h60
  text "X" at 13082.46,2792.9 h60
  text "V. SCORE" at 13260.46,2792.9 h60
  text "CERTIFICATION:" at 11333.46,2663.77 h60
  text "MATERIALS AND WORKMANSHIP FOR ALL PCBS" at 12058.46,2663.77 h60
  text "TO MEET OR EXCEED THE REQUIREMENTS OF:" at 12058.46,2569.71 h60
  text "X" at 11695.97,2441.08 h60
  text "ANSI IPC-A-600F CLASS ->" at 11823.96,2441.08 h60
  text "X" at 13471.97,2441.08 h60
  text "2" at 13581.96,2441.08 h60
  text "1" at 13266.96,2439.58 h60
  text "3" at 13935.96,2439.58 h60
  text "X" at 12507.97,2293.39 h60
  text "RoHS" at 12635.96,2293.39 h60
  text "OTHER" at 13280.36,2293.39 h60
  text "PER ORDER" at 13677.42,2293.39 h60
  text "ALL BOARDS MUST MEET OR EXCEED UL94-V0 REQUIREMENTS." at 11361,2139.57 h60
  text "PCB MUST BEAR THE UL94V-0 UL REGISTERED MATERIAL ID NUMBER" at 11361,2023.5 h60
  text "ADDITIONAL REQUIREMENTS:" at 11333.46,1854.08 h60
  text "MICROSECTION:" at 11408.23,1746.95 h60
  text "YES" at 12313.96,1746.95 h60
  text "REQUIRED" at 13175.46,1602.62 h60
  text "BARE BOARD ELEC. TEST:" at 11408.23,1599.76 h60
  text "NONE" at 12713.96,1599.76 h60
  text "X" at 13057.46,1599.76 h60
  text "PER ORDER" at 13767.46,1599.76 h60
  text "XX MIL VIAS REQUIRE NON-CONDUCTIVE FILL AND PLANARIZE" at 11576.38,1394.82 h59
  text "XX MIL VIAS REQUIRE CONDUCTIVE FILL AND PLANARIZE" at 11584.38,1290.84 h60
  text "OUTER XX MIL TRACES REQUIRE 50 OHM SINGLE-ENDED IMPEDANCE" at 11583.39,1127.46 h58
  text "LAYER 2 & 3 (INNER LAYERS) XX MIL WIDE, XX MIL SPACE / TRACES REQUIRE 100 OHM DIFFERENTIAL IMPEDANCE" at 11575.39,891.74 h60
  text ".Layer_Name" at 577,-858.49 h60
M11 Gerber Information:
  lines w10: -292,-930.17 6308,-930.17 ; -292,-726.83 6310,-726.83 ; -292,-523.5 -292,-1133.5 3713,-1133.5 6310,-1133.5 6310,-523.5 -291.5,-523.5 -291.5,-1133.5 1284,-1133.5 ; 2173,-1133.5 2173,-523.5 ; 3440,-726.83 3440,-523.5 ; 4280,-726.83 4280,-523.5 ; 4902,-1140 4902,-937.17
  text "ALL ARTWORK VIEWED FROM TOP SIDE" at -228.5,-655.67 h60
  text "BOARD #:" at 2248,-655.67 h60
  text ".PRJ_Number" at 2793.5,-655.67 h60
  text "REV:" at 3638,-655.67 h60
  text ".PCB_Rev" at 3929.5,-655.67 h60
  text "SVN REV:" at 4476,-655.67 h60
  text ".VersionControl_RevNumber" at 4982,-655.67 h60
  text "LAYER NAME =" at -228.5,-858.49 h60
  text "TID #:" at 2248,-859 h60
  text ".TID" at 2793.5,-859 h60
  text "PLOT NAME =" at -228.5,-1064.34 h60
  text ".plot_File_Name" at 577,-1064.34 h60
  text "GENERATED    :" at 2250,-1064.34 h60
  text ".Print_Date" at 3119.5,-1064.34 h60
  text ".Print_Time" at 3848.5,-1064.34 h60
  text "TEXAS INSTRUMENTS" at 5113,-1064.34 h60
M12 Stackup:
  drawing of 295 lines, arcs and shapes, not listed
  text "Layer" at 9821.59,7874.94 h60
  text "Name" at 10231.51,7874.94 h60
  text "Material" at 11161.25,7874.94 h60
  text "Thickness" at 12021.02,7874.94 h60
  text "Constant" at 12670.85,7874.94 h60
  text "Board Layer Stack" at 13240.71,7874.94 h60
  text "Top Overlay" at 10231.51,7754.94 h60
  text "Top Solder" at 10231.51,7634.94 h60
  text "Solder Resist" at 11161.25,7634.94 h60
  text "0.40mil" at 12021.02,7634.94 h60
  text "3.5" at 12670.85,7634.94 h60
  text "1" at 9821.59,7514.94 h60
  text "Top Layer" at 10231.51,7514.94 h60
  text "2.80mil" at 12021.02,7514.94 h60
  text "Dielectric 1" at 10231.51,7394.94 h60
  text "PP-006" at 11161.25,7394.94 h60
  text "5.60mil" at 12021.02,7394.94 h60
  text "4.1" at 12670.85,7394.94 h60
  text "2" at 9821.59,7274.94 h60
  text "Layer 1" at 10231.51,7274.94 h60
  text "CF-004" at 11161.25,7274.94 h60
  text "2.80mil" at 12021.02,7274.94 h60
  text "Dielectric1" at 10231.51,7154.94 h60
  text "FR-4 High Tg" at 11161.25,7154.94 h60
  text "29.80mil" at 12021.02,7154.94 h60
  text "4.8" at 12670.85,7154.94 h60
  text "3" at 9821.59,7034.94 h60
  text "Layer 2" at 10231.51,7034.94 h60
  text "CF-004" at 11161.25,7034.94 h60
  text "2.80mil" at 12021.02,7034.94 h60
  text "Dielectric 2" at 10231.51,6914.94 h60
  text "PP-006" at 11161.25,6914.94 h60
  text "5.60mil" at 12021.02,6914.94 h60
  text "4.1" at 12670.85,6914.94 h60
  text "4" at 9821.59,6794.94 h60
  text "Bottom Layer" at 10231.51,6794.94 h60
  text "2.80mil" at 12021.02,6794.94 h60
  text "Bottom Solder" at 10231.51,6674.94 h60
  text "Solder Resist" at 11161.25,6674.94 h60
  text "0.40mil" at 12021.02,6674.94 h60
  text "3.5" at 12670.85,6674.94 h60
  text "Bottom Overlay" at 10231.51,6554.94 h60
  text ".Layer_Name" at 577,-858.49 h60
M13 Component Bodies Top:
  text ".Layer_Name" at 577,-858.49 h60
M14 Component Bodies Bottom:
  text ".Layer_Name" at 577,-858.49 h60
M15 Courtyards Top:
  text ".Layer_Name" at 577,-858.49 h60
M16 Courtyards Bottom:
  text ".Layer_Name" at 577,-858.49 h60
Drill Drawing:
  circle w10: c5363.54,3042.66 r27.56
  lines w10: 5335.98,3139.13 5391.1,3139.13 5391.1,3194.25 5335.98,3194.25 5335.98,3139.13 ; 5335.98,3263.15 5363.54,3276.94 5391.1,3263.15 5377.32,3290.72 5391.1,3318.28 5363.54,3304.5 5335.98,3318.28 5349.76,3290.72 5335.98,3263.15
  lines w12: 5286,2977.89 8512.8,2977.89 ; 5286,3349.97 8512.8,3349.97 ; 5623.36,2853.87 5623.36,3474 ; 5955.06,2853.87 5955.06,3474 ; 6590.91,2853.87 6590.91,3474 ; 6849.71,2853.87 6849.71,3474 ; 7224.46,2853.87 7224.46,3474 ; 7947,2853.87 7947,3474 ; 5286,2853.87 8512.8,2853.87 8512.8,3474 5286,3474 5286,2853.87
  text "Symbol" at 5360.42,3387.18 h72
  text "Quantity" at 5660.57,3387.18 h72
  text "Finished Hole Size" at 5992.26,3387.18 h72
  text "Plated" at 6628.12,3387.18 h72
  text "Hole Type" at 6886.92,3387.18 h72
  text "Drill Layer Pair" at 7261.67,3387.18 h72
  text "Hole Tolerance" at 7984.21,3387.18 h72
  text "17" at 5660.57,3263.15 h60
  text "24.00mil (0.610mm)" at 5992.26,3263.15 h60
  text "PTH" at 6628.12,3263.15 h60
  text "Round" at 6886.92,3263.15 h60
  text "Top Layer - Bottom Layer" at 7261.67,3263.15 h60
  text "6" at 5660.57,3139.13 h60
  text "39.37mil (1.000mm)" at 5992.26,3139.13 h60
  text "PTH" at 6628.12,3139.13 h60
  text "Round" at 6886.92,3139.13 h60
  text "Top Layer - Bottom Layer" at 7261.67,3139.13 h60
  text "4" at 5660.57,3015.1 h60
  text "64.96mil (1.650mm)" at 5992.26,3015.1 h60
  text "PTH" at 6628.12,3015.1 h60
  text "Round" at 6886.92,3015.1 h60
  text "Top Layer - Bottom Layer" at 7261.67,3015.1 h60
  text "27 Total" at 5660.57,2891.07 h60
  text ".Layer_Name" at 577,-858.49 h60
M17 Embedded Cavity:
  text ".Layer_Name" at 577,-858.49 h60
M18 Embedded Assembly:
  text ".Layer_Name" at 577,-858.49 h60
M19 Embedded Keepout:
  text ".Layer_Name" at 577,-858.49 h60

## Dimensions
0,0 to 2300,0 on M2 Board Dimensions
0,0 to 0,940 on M2 Board Dimensions
0,-400 to 1000,-400 on M2 Board Dimensions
